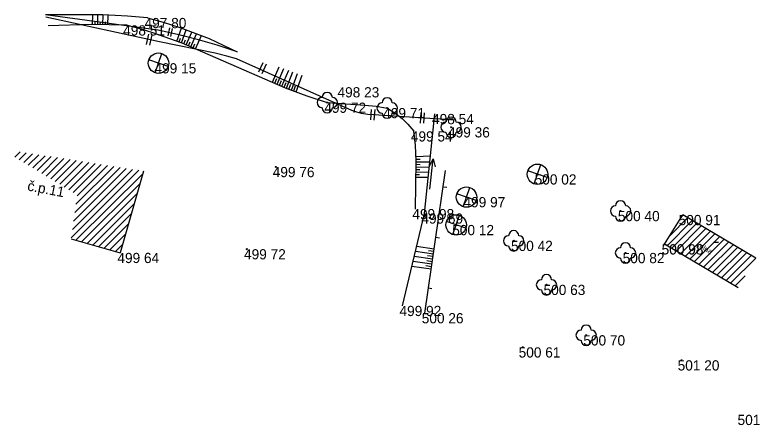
# Model space of a CAD drawing. Extents: x -554123 to -553118, y -1076825 to -1073672.
# Drawn here: x -553264.9 to -553192.3, y -1076774.9 to -1076734.7 of the extents above; entities that cross this region are included whole.
import ezdxf

# ---------------------------------------------------------------- set-up
doc = ezdxf.new("R2010")
doc.units = 0
for name, color, linetype in [('1', 7, 'Continuous'), ('12', 7, 'Continuous'), ('14', 7, 'Continuous'), ('26', 7, 'Continuous'), ('27', 7, 'Continuous'), ('28', 7, 'Continuous'), ('32', 7, 'Continuous'), ('34', 7, 'Continuous'), ('47', 7, 'Continuous'), ('52', 7, 'Continuous'), ('54', 7, 'Continuous'), ('6', 7, 'Continuous'), ('62', 7, 'Continuous')]:
    doc.layers.add(name, color=color, linetype=linetype)

# ---------------------------------------------------------------- blocks, each defined once
blk = doc.blocks.new('POINT_DISPLAY')
blk.add_line((0, 0), (0, 0))
blk = doc.blocks.new('STJ')
at = {"layer": '34'}
for p, q in [((-0.327, -0.945), (0.327, 0.945)), ((0.945, -0.327), (-0.945, 0.327))]:
    blk.add_line(p, q, dxfattribs=at)
for radius in [1, 0.0496]:
    blk.add_circle((0, 0), radius, dxfattribs=at)
blk = doc.blocks.new('STL')
at = {"layer": '34'}
blk.add_circle((0, 0), 0.05, dxfattribs=at)
for centre, start, end in [((0, 0.5), 0, 180), ((-0.5, 0), 90, 270), ((0.5, 0), 270, 90), ((0, -0.5), 180, 0)]:
    blk.add_arc(centre, 0.5, start, end, dxfattribs=at)
blk = doc.blocks.new('T')
at = {"layer": '6'}
blk.add_circle((0, 0), 0.05, dxfattribs=at)
blk = doc.blocks.new('BN')
at = {"layer": '47'}
blk.add_line((-0.25, 0), (0.25, 0), dxfattribs=at)
blk = doc.blocks.new('VOTOK')
at = {"layer": '28'}
for p, q in [((-3.001, 0), (0, 0)), ((-0.75, 0.282), (0, 0)), ((0, 0), (-0.75, -0.28))]:
    blk.add_line(p, q, dxfattribs=at)
blk = doc.blocks.new('ROV')
at = {"layer": '62'}
for p, q in [((-0.348, -0.51), (-0.348, 0.51)), ((0, -0.51), (0, 0.51))]:
    blk.add_line(p, q, dxfattribs=at)

msp = doc.modelspace()

# ---------------------------------------------------------------- linework, layer by layer
at = {"layer": '12'}
for p, q in [((-553224.77, -1076763.9), (-553222.72, -1076749.93)), ((-553222.955, -1076751.532), (-553222.609, -1076751.583)), ((-553223.681, -1076756.479), (-553223.335, -1076756.53)), ((-553224.407, -1076761.426), (-553224.061, -1076761.477))]:
    msp.add_line(p, q, dxfattribs=at)
at = {"layer": '14'}
for p, q in [((-553252.299, -1076749.992), (-553254.56, -1076758)), ((-553201.29, -1076757.16), (-553199.52, -1076754.29)), ((-553192.377, -1076758.52), (-553199.52, -1076754.29)), ((-553259.372, -1076756.641), (-553254.56, -1076758)), ((-553194.095, -1076761.421), (-553201.29, -1076757.16))]:
    msp.add_line(p, q, dxfattribs=at)
at = {"layer": '26'}
for p, q in [((-553257.269, -1076735.645), (-553257.248, -1076734.695)), ((-553256.769, -1076735.656), (-553256.748, -1076734.694)), ((-553256.269, -1076735.667), (-553256.247, -1076734.696)), ((-553257.019, -1076735.651), (-553257.013, -1076735.364)), ((-553256.519, -1076735.662), (-553256.513, -1076735.371)), ((-553256.019, -1076735.673), (-553256.013, -1076735.383)), ((-553255.769, -1076735.678), (-553255.748, -1076734.72)), ((-553249.04, -1076737.261), (-553248.587, -1076736.001)), ((-553248.57, -1076737.43), (-553248.119, -1076736.174)), ((-553248.11, -1076737.628), (-553247.566, -1076736.377)), ((-553247.652, -1076737.827), (-553247.097, -1076736.549)), ((-553247.193, -1076738.026), (-553246.627, -1076736.722)), ((-553248.805, -1076737.346), (-553248.669, -1076736.968)), ((-553248.34, -1076737.528), (-553248.178, -1076737.157)), ((-553247.881, -1076737.727), (-553247.716, -1076737.348)), ((-553247.422, -1076737.927), (-553247.254, -1076737.539)), ((-553239.668, -1076741.295), (-553239.014, -1076739.789)), ((-553239.21, -1076741.495), (-553238.543, -1076739.959)), ((-553238.751, -1076741.694), (-553238.071, -1076740.129)), ((-553238.289, -1076741.885), (-553237.689, -1076740.266)), ((-553237.82, -1076742.059), (-553237.219, -1076740.436)), ((-553239.439, -1076741.395), (-553239.241, -1076740.939)), ((-553238.98, -1076741.594), (-553238.778, -1076741.129)), ((-553237.352, -1076742.233), (-553236.749, -1076740.605)), ((-553238.522, -1076741.794), (-553238.316, -1076741.32)), ((-553238.055, -1076741.972), (-553237.875, -1076741.486)), ((-553237.586, -1076742.146), (-553237.405, -1076741.658)), ((-553225.635, -1076748.581), (-553224.213, -1076748.517)), ((-553225.623, -1076748.83), (-553225.208, -1076748.812)), ((-553225.616, -1076749.08), (-553224.272, -1076749.099)), ((-553225.626, -1076749.83), (-553225.243, -1076749.835)), ((-553225.623, -1076749.58), (-553224.324, -1076749.598)), ((-553225.619, -1076749.33), (-553225.223, -1076749.335)), ((-553225.637, -1076750.58), (-553224.426, -1076750.597)), ((-553225.633, -1076750.33), (-553225.264, -1076750.335)), ((-553225.63, -1076750.08), (-553224.375, -1076750.097)), ((-553223.922, -1076758.122), (-553225.675, -1076757.865)), ((-553223.85, -1076757.627), (-553225.559, -1076757.376)), ((-553223.886, -1076757.875), (-553224.405, -1076757.798)), ((-553223.995, -1076758.617), (-553225.791, -1076758.353)), ((-553223.958, -1076758.369), (-553224.491, -1076758.291)), ((-553224.14, -1076759.606), (-553226.023, -1076759.33)), ((-553224.067, -1076759.111), (-553225.907, -1076758.841)), ((-553224.104, -1076759.359), (-553224.662, -1076759.277)), ((-553224.031, -1076758.864), (-553224.576, -1076758.784))]:
    msp.add_line(p, q, dxfattribs=at)
at = {"layer": '27'}
for points in [[(-553253.9, -1076735.72), (-553257.406, -1076735.642), (-553261.62, -1076735.78)], [(-553253.9, -1076735.72), (-553252.657, -1076736.029), (-553251.401, -1076736.413), (-553248.54, -1076737.441), (-553238.431, -1076741.833), (-553236.314, -1076742.617), (-553234.31, -1076743.29)], [(-553234.31, -1076743.29), (-553230.621, -1076743.541), (-553229.527, -1076743.654), (-553228.44, -1076743.82)], [(-553228.44, -1076743.82), (-553227.704, -1076744.29), (-553226.976, -1076744.848), (-553226.422, -1076745.389), (-553225.85, -1076746.1)], [(-553225.68, -1076753.71), (-553225.615, -1076749.014), (-553225.685, -1076747.463), (-553225.85, -1076746.1)]]:
    msp.add_lwpolyline(points, dxfattribs=at)
at = {"layer": '28'}
for p, q in [((-553224.79, -1076754.14), (-553223.79, -1076744.4)), ((-553226.94, -1076763.19), (-553224.79, -1076754.14))]:
    msp.add_line(p, q, dxfattribs=at)
for points in [[(-553251.91, -1076735), (-553253.868, -1076734.813), (-553256.281, -1076734.694), (-553261.894, -1076734.7)], [(-553251.91, -1076735), (-553250.36, -1076735.42), (-553248.749, -1076735.942), (-553245.854, -1076737.006), (-553243.12, -1076738.31)]]:
    msp.add_lwpolyline(points, dxfattribs=at)
at = {"layer": '32'}
for p, q in [((-553264.882, -1076748.617), (-553264.368, -1076748.102)), ((-553264.443, -1076748.884), (-553263.757, -1076748.198)), ((-553264.003, -1076749.151), (-553263.145, -1076748.294)), ((-553263.563, -1076749.419), (-553262.534, -1076748.389)), ((-553263.123, -1076749.686), (-553261.922, -1076748.485)), ((-553262.683, -1076749.953), (-553261.311, -1076748.581)), ((-553262.243, -1076750.22), (-553260.7, -1076748.677)), ((-553261.804, -1076750.488), (-553260.088, -1076748.772)), ((-553261.364, -1076750.755), (-553259.477, -1076748.868)), ((-553260.924, -1076751.022), (-553258.866, -1076748.964)), ((-553260.484, -1076751.289), (-553258.254, -1076749.06)), ((-553260.044, -1076751.557), (-553257.643, -1076749.155)), ((-553259.604, -1076751.824), (-553257.031, -1076749.251)), ((-553259.356, -1076756.525), (-553252.752, -1076749.921)), ((-553259.243, -1076755.705), (-553253.363, -1076749.825)), ((-553259.164, -1076752.091), (-553256.42, -1076749.347)), ((-553259.13, -1076754.885), (-553253.975, -1076749.73)), ((-553259.017, -1076754.065), (-553254.586, -1076749.634)), ((-553258.905, -1076753.245), (-553255.197, -1076749.538)), ((-553258.792, -1076752.426), (-553255.809, -1076749.442)), ((-553258.898, -1076756.775), (-553252.371, -1076750.248)), ((-553258.347, -1076756.93), (-553252.649, -1076751.233)), ((-553257.796, -1076757.086), (-553252.928, -1076752.218)), ((-553257.244, -1076757.242), (-553253.206, -1076753.204)), ((-553256.693, -1076757.398), (-553253.484, -1076754.189)), ((-553201.055, -1076757.299), (-553198.595, -1076754.838)), ((-553200.753, -1076756.29), (-553199.039, -1076754.575)), ((-553199.615, -1076754.445), (-553199.483, -1076754.312)), ((-553256.141, -1076757.553), (-553253.762, -1076755.174)), ((-553200.611, -1076757.562), (-553198.15, -1076755.101)), ((-553200.167, -1076757.825), (-553197.706, -1076755.364)), ((-553199.723, -1076758.088), (-553197.262, -1076755.627)), ((-553255.59, -1076757.709), (-553254.04, -1076756.159)), ((-553199.279, -1076758.351), (-553196.818, -1076755.89)), ((-553198.835, -1076758.614), (-553196.374, -1076756.153)), ((-553198.391, -1076758.877), (-553195.93, -1076756.416)), ((-553255.039, -1076757.865), (-553254.319, -1076757.145)), ((-553197.947, -1076759.14), (-553195.486, -1076756.679)), ((-553197.503, -1076759.403), (-553195.042, -1076756.942)), ((-553197.058, -1076759.666), (-553194.598, -1076757.205)), ((-553196.614, -1076759.929), (-553194.153, -1076757.468)), ((-553196.17, -1076760.192), (-553193.709, -1076757.731)), ((-553195.726, -1076760.455), (-553193.265, -1076757.994)), ((-553195.282, -1076760.718), (-553192.821, -1076758.257)), ((-553194.838, -1076760.981), (-553192.377, -1076758.52)), ((-553194.394, -1076761.244), (-553193.404, -1076760.254))]:
    msp.add_line(p, q, dxfattribs=at)
at = {"layer": '62'}
for p, q in [((-553250.84, -1076736.21), (-553261.894, -1076734.7)), ((-553250.72, -1076737.35), (-553261.839, -1076734.916)), ((-553248.828, -1076736.654), (-553250.84, -1076736.21)), ((-553246.903, -1076737.147), (-553248.828, -1076736.654)), ((-553245.283, -1076738.463), (-553250.72, -1076737.35)), ((-553245.072, -1076737.664), (-553246.903, -1076737.147)), ((-553243.12, -1076738.31), (-553245.072, -1076737.664)), ((-553244.121, -1076738.733), (-553245.283, -1076738.463)), ((-553243.19, -1076739), (-553244.121, -1076738.733)), ((-553231.917, -1076744.051), (-553243.19, -1076739)), ((-553231.424, -1076744.233), (-553231.917, -1076744.051)), ((-553230.96, -1076744.36), (-553231.424, -1076744.233)), ((-553230.332, -1076744.444), (-553230.96, -1076744.36)), ((-553229.751, -1076744.485), (-553230.332, -1076744.444)), ((-553221.76, -1076745), (-553229.751, -1076744.485))]:
    msp.add_line(p, q, dxfattribs=at)

# ---------------------------------------------------------------- block references
at = {"layer": '1'}
for p in [(-553251.91, -1076735), (-553253.9, -1076735.72), (-553250.82, -1076739.43), (-553233.03, -1076741.78), (-553234.31, -1076743.29), (-553228.44, -1076743.82), (-553223.79, -1076744.4), (-553225.85, -1076746.1), (-553222.19, -1076745.7), (-553239.35, -1076749.59), (-553213.73, -1076750.31), (-553220.68, -1076752.54), (-553225.68, -1076753.71), (-553224.79, -1076754.14), (-553205.6, -1076753.9), (-553199.52, -1076754.29), (-553221.69, -1076755.27), (-553216.06, -1076756.82), (-553201.3, -1076757.16), (-553201.29, -1076757.16), (-553242.17, -1076757.64), (-553254.56, -1076758), (-553205.12, -1076758.01), (-553212.85, -1076761.13), (-553226.94, -1076763.19), (-553224.77, -1076763.9), (-553208.97, -1076766.07), (-553215.18, -1076767.25), (-553199.63, -1076768.52), (-553193.77, -1076773.86)]:
    msp.add_blockref('POINT_DISPLAY', p, dxfattribs=at)
at = {"layer": '28', "xscale": 0.9999991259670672, "yscale": 0.9999991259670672, "rotation": 83.72206501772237}
msp.add_blockref('VOTOK', (-553223.954, -1076748.788), dxfattribs=at)
at = {"layer": '32'}
msp.add_blockref('POINT_DISPLAY', (-553192.377, -1076758.52), dxfattribs=at)
at = {"layer": '34'}
for name, p in [('STJ', (-553250.82, -1076739.43)), ('STL', (-553234.31, -1076743.29)), ('STL', (-553228.44, -1076743.82)), ('STL', (-553222.19, -1076745.7)), ('STJ', (-553213.73, -1076750.31)), ('STJ', (-553220.68, -1076752.54)), ('STL', (-553205.6, -1076753.9)), ('STJ', (-553221.69, -1076755.27)), ('STL', (-553216.06, -1076756.82)), ('STL', (-553205.12, -1076758.01)), ('STL', (-553212.85, -1076761.13)), ('STL', (-553208.97, -1076766.07))]:
    msp.add_blockref(name, p, dxfattribs=at)
at = {"layer": '47'}
msp.add_blockref('BN', (-553196.269, -1076756.949), dxfattribs=at)
at = {"layer": '52'}
for p, xscale, yscale, rotation in [((-553249.525, -1076736.419), 0.7999993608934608, 0.7999993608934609, -12.444341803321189), ((-553251.923, -1076737.087), 1.0000021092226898, 1.0000021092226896, 167.65246632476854)]:
    msp.add_blockref('ROV', p, dxfattribs=dict(at, xscale=xscale, yscale=yscale, rotation=rotation))
at = {"layer": '6'}
for p in [(-553239.35, -1076749.59), (-553201.3, -1076757.16), (-553242.17, -1076757.64), (-553215.18, -1076767.25), (-553199.63, -1076768.52)]:
    msp.add_blockref('T', p, dxfattribs=at)
at = {"layer": '62'}
for p, xscale, yscale, rotation in [((-553240.462, -1076739.968), 0.9999991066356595, 0.9999991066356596, -24.13535013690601), ((-553230.046, -1076744.464), 0.9999987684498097, 0.9999987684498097, 175.96336960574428), ((-553225.196, -1076744.779), 0.9999980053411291, 0.9999980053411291, 176.3126077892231)]:
    msp.add_blockref('ROV', p, dxfattribs=dict(at, xscale=xscale, yscale=yscale, rotation=rotation))

# ---------------------------------------------------------------- texts
at = {"layer": '52'}
msp.add_text('kolna', height=0.5, rotation=329.36527, dxfattribs=at).set_placement((-553198.23, -1076757.307))
at = {"layer": '54'}
msp.add_text('č.p.11', height=1, rotation=349.26507, dxfattribs=at).set_placement((-553263.708, -1076751.883))
at = {"layer": '6'}
for s, p in [('497 80 ', (-553252.184, -1076736)), ('498 51 ', (-553254.281, -1076736.72)), ('499 15 ', (-553251.215, -1076740.43)), ('498 23 ', (-553233.304, -1076742.78)), ('499 72 ', (-553234.594, -1076744.29)), ('499 71 ', (-553228.831, -1076744.82)), ('498 54 ', (-553224.052, -1076745.4)), ('499 54 ', (-553226.124, -1076747.1)), ('499 36 ', (-553222.488, -1076746.7)), ('499 76 ', (-553239.646, -1076750.59)), ('500 02 ', (-553214.01, -1076751.31)), ('499 97 ', (-553220.976, -1076753.54)), ('499 98 ', (-553225.978, -1076754.71)), ('499 69 ', (-553225.1, -1076755.14)), ('500 40 ', (-553205.868, -1076754.9)), ('500 91 ', (-553199.917, -1076755.29)), ('500 12 ', (-553222.077, -1076756.27)), ('500 42 ', (-553216.326, -1076757.82)), ('500 98 ', (-553201.59, -1076758.16)), ('500 98 ', (-553201.58, -1076758.16)), ('499 72 ', (-553242.454, -1076758.64)), ('499 64 ', (-553254.846, -1076759)), ('500 82 ', (-553205.398, -1076759.01)), ('500 63 ', (-553213.14, -1076762.13)), ('499 92 ', (-553227.238, -1076764.19)), ('500 26 ', (-553225.06, -1076764.9)), ('500 70 ', (-553209.248, -1076767.07)), ('500 61 ', (-553215.577, -1076768.25)), ('501 20 ', (-553200.017, -1076769.52)), ('501 64 ', (-553194.155, -1076774.86))]:
    msp.add_text(s, height=1, dxfattribs=at).set_placement(p)

doc.saveas('drawing.dxf')
